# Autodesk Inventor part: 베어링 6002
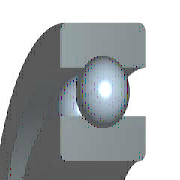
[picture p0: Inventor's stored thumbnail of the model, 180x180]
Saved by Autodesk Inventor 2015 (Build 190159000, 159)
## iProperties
IsCustomPart: 0
Created: 2015-10
Part Number: 베어링 6002
Material: 강철, 연강
Description: 깊은 그루브 볼 베어링
Document SubType Name: Modeling
Standard: KS B 2023
Designer: mdu
Standards Organization: KS
Language: ko-KR
Size Designation: 6002 - 15 x 32 x 9
Categories: <MemberInstance><Categories><Category DisplayName="샤프트 부품" InternalName="7f7aeb1f-a693-4053-b835-cee3144e0d98" Mnemonic="SHFT"><Category DisplayName="베어링" Inter
Density: 7.86 g/cm^3
Mass: 29.8124 g
Surface Area: 39.9079 cm^2
Volume: 3.79292 cm^3
Appearance: 강철
Author: mdu
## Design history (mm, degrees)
sketch "스케치" dims "d0" = 4.42 (= -0.26 x WD + 0.26 x BD)
  geometry: L1 (2.29, 11.75)-(6.71, 11.75); L2 (4.5, 11.75)-(4.5, 9.54); L3 (4.5, 11.75)-(4.5, 13.96); L4 (2.858, 10.271)-(0, 10.271); L5 (0, 7.5)-(9, 7.5); L6 (2.858, 13.229)-(0, 13.229); L7 (0, 16)-(9, 16); L8 (9, 7.5)-(9, 10.271); L9 (6.142, 10.271)-(9, 10.271); L10 (6.142, 13.229)-(9, 13.229); L11 (9, 16)-(9, 13.229); L12 (-1.4, 0)-(8.4, 0) reference; L13 (0, -0.3)-(0, 5.3) reference
  constraints: 22 end point, 4 point on line, 2 collinear, 2 perpendicular, 2 symmetric about line, 1 midpoint, 1 parallel, 14 other
  dimensions: "d9" = 15 diameter of L5 L12 (= WD); "d11" = 32 diameter of L7 L12 (= BD); "d12" = 9 distance between parallel lines of L8 L13 (= KB); "d13" = 20.542 diameter of L9 L12 (= 0.326 x BD + 0.674 x WD)
revolve "본체" stored, may be unused: angle "d6" = 90 deg
revolve "볼" stored, may be unused: angle "d7" = 90 deg
pattern_circular "IDS_ARRAYBALL[SIMPL:T]" dims angle "d3" = 360 deg
body "Solid1"
fillet "모깎기1" dims "d1" = 0.3 (= KRS)
other parameters: "WD" = 15 [user parameter; used in 5 equation terms], "BD" = 32 [user parameter; used in 5 equation terms], "KB" = 9 [user parameter; used in 1 equation term], "KRS" = 0.3 [user parameter; used in 1 equation term], "d4" = 0, "d5" = 0, "d8" = 0, "d14" = 0, "d15" = 0, "BBA" = 0 [user parameter], "BC0" = 2850000 [user parameter], "BC" = 5590000 [user parameter], "BR" = 16 (= 0.5 x BD) [user parameter], "WR" = 7.5 (= 0.5 x WD) [user parameter]
